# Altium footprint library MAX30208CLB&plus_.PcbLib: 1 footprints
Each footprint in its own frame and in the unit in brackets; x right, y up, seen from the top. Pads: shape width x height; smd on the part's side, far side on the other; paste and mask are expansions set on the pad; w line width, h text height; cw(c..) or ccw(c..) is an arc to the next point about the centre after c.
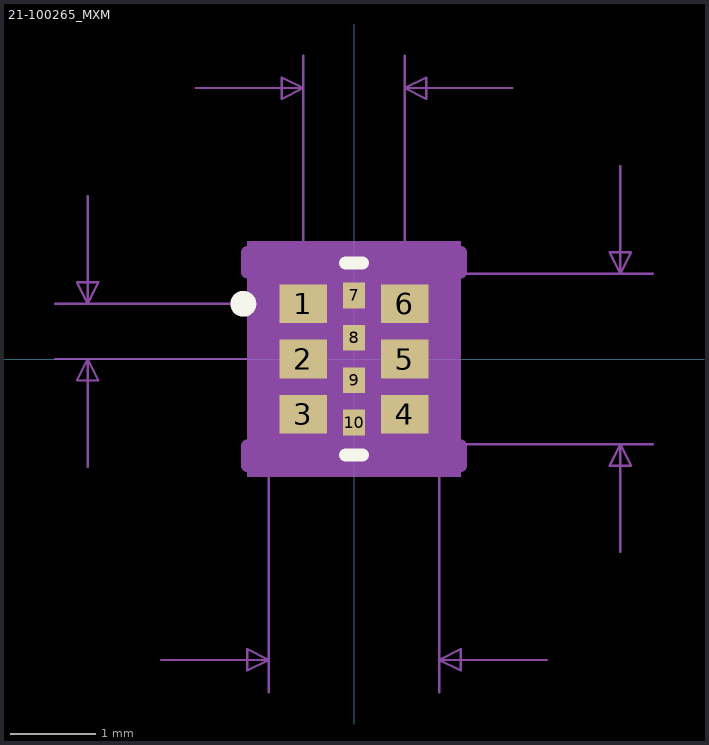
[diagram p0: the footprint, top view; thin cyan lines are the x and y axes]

## 21-100265_MXM [mil]
pads (10):
  rect 22x18 smd paste-9 mask+0: 1(-23.5,25.59) 2(-23.5,0) 3(-23.5,-25.59) 4(23.5,-25.59) 5(23.5,0) 6(23.5,25.59)
  rect 10x12 smd: 7(0,29.53) 8(0,9.84) 9(0,-9.84) 10(0,-29.53)
Top Overlay:
  circle w6: c-51.3,25.59 r3
  lines w6: -3.93,-44.5 3.93,-44.5 ; -3.93,44.5 3.93,44.5
Mechanical 5:
  region: 49.5,-54.5 -49.5,-54.5 -49.5,54.5 49.5,54.5
Mechanical 7:
  lines w1: -138.5,0 -23.5,0 ; -138.5,25.59 -23.5,25.59 -23.5,140.59 ; -123.5,-50 -123.5,0 ; -123.5,75.59 -123.5,25.59 ; -89.5,-139.5 -39.5,-139.5 ; -73.5,125.59 -23.5,125.59 ; -39.5,-154.5 -39.5,-39.5 ; 23.5,25.59 23.5,140.59 ; 39.5,-154.5 39.5,-39.5 138.5,-39.5 ; 39.5,39.5 138.5,39.5 ; 73.5,125.59 23.5,125.59 ; 89.5,-139.5 39.5,-139.5 ; 123.5,-89.5 123.5,-39.5 ; 123.5,89.5 123.5,39.5 ; -123.5,0 -128.5,-10 -118.5,-10 -123.5,0 ; -123.5,25.59 -128.5,35.59 -118.5,35.59 -123.5,25.59 ; -39.5,-139.5 -49.5,-134.5 -49.5,-144.5 -39.5,-139.5 ; -23.5,125.59 -33.5,130.59 -33.5,120.59 -23.5,125.59 ; 23.5,125.59 33.5,130.59 33.5,120.59 23.5,125.59 ; 39.5,-139.5 49.5,-134.5 49.5,-144.5 39.5,-139.5 ; 123.5,-39.5 118.5,-49.5 128.5,-49.5 123.5,-39.5 ; 123.5,39.5 118.5,49.5 128.5,49.5 123.5,39.5
  text "Default Padstyle: RX22Y18D0T" at -350,-399.5 h50
  text "Alt 1 Padstyle: OX60Y90D30P" at -337.5,-579.5 h50
  text "Alt 2 Padstyle: OX90Y60D30P" at -337.5,-639.5 h50
  text "0.047in/1.194mm" at -93.75,145.59 h25
  text "0.026in/0.65mm" at -318.5,0.3 h25
  text "0.079in/2.007mm" at 143.5,-12.5 h25
  text "0.079in/2.007mm" at -93.75,-184.5 h25
Mechanical 13:
  circle w0: c-12.5,25.59 r3
  lines w0: -12,39.5 ccw(c0,39.5) 12,39.5
  lines w1: -39.5,-39.5 39.5,-39.5 39.5,39.5 -39.5,39.5 -39.5,-39.5
Mechanical 15:
  region: -49.5,-40.39 -44.5,-40.39 -44.5,40.39 -49.5,40.39 -49.5,49.5 49.5,49.5 49.5,40.39 44.5,40.39 44.5,-40.39 49.5,-40.39 49.5,-49.5 -49.5,-49.5
  lines w6: -49.5,-49.5 -49.5,-40.39 -44.5,-40.39 -44.5,40.39 -49.5,40.39 -49.5,49.5 49.5,49.5 49.5,40.39 44.5,40.39 44.5,-40.39 49.5,-40.39 49.5,-49.5 -49.5,-49.5
3D body: height 10, standoff 0, extent 0,0 10,10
